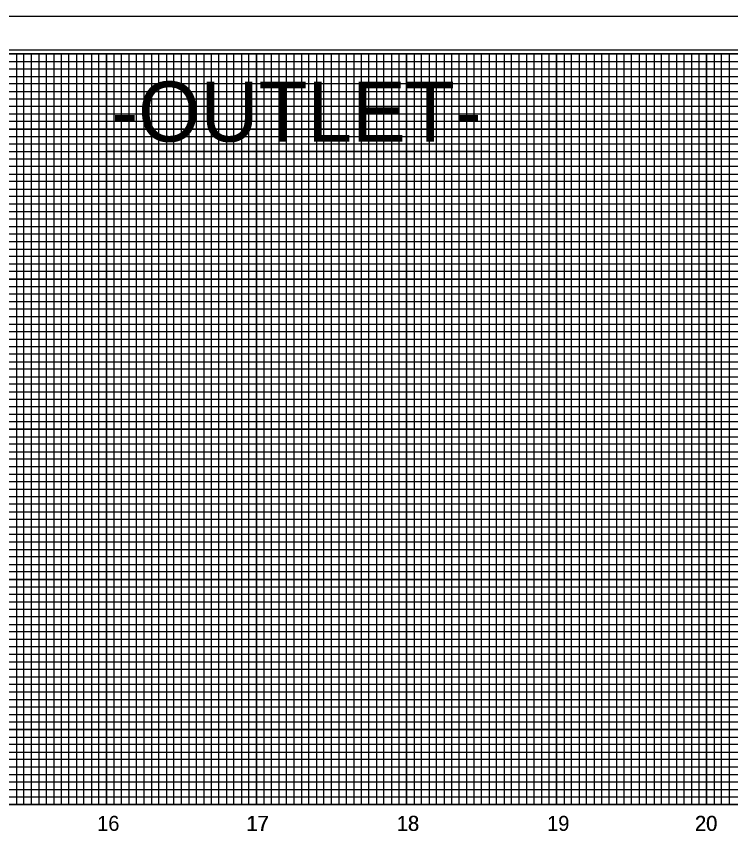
# Model space of a CAD drawing. Extents: x 1779926 to 1781610, y 602514 to 621564.
# Drawn here: x 1780683 to 1781159, y 603068 to 603614 of the extents above; entities that cross this region are included whole.
import ezdxf

# ---------------------------------------------------------------- set-up
doc = ezdxf.new("R2010")
doc.units = 0
for name, color, linetype in [('Exist Vertical Profile Horizontal Axis Label Major', 7, 'Continuous'), ('Exist Vertical Profile Vertical Axis Label', 7, 'Continuous'), ('Prop Grid Mask', 7, 'Continuous'), ('Scratch_Level_0', 7, 'Continuous'), ('Sheet DOT Grid CELL', 7, 'Continuous'), ('Sheet Layout Profile Border Port 1', 7, 'Continuous'), ('Sheet Plot Border Inside CELL', 7, 'Continuous'), ('Sheet Plot Border Outside CELL', 7, 'Continuous'), ('Sheet Profile CELL', 7, 'Continuous'), ('Sheet Profile Grid Major CELL', 7, 'Continuous'), ('Sheet Profile Grid Middle CELL', 7, 'Continuous'), ('Sheet Profile Grid Minor CELL', 7, 'Continuous')]:
    doc.layers.add(name, color=color, linetype=linetype)

msp = doc.modelspace()

# ---------------------------------------------------------------- linework, layer by layer
at = {"layer": 'Prop Grid Mask'}
msp.add_lwpolyline([(1780742.96, 603574.45), (1780997.96, 603574.45), (1780997.96, 603524.45), (1780742.96, 603524.45)], close=True, dxfattribs=at)
at = {"layer": 'Scratch_Level_0'}
msp.add_lwpolyline([(1780142.96, 603089.44), (1780142.96, 603589.44), (1781392.96, 603589.44), (1781392.96, 603364.44), (1781542.96, 603364.44), (1781542.96, 603089.44)], close=True, dxfattribs=at)
at = {"layer": 'Sheet DOT Grid CELL'}
for p, q in [((1780692.96, 603089.45), (1780692.96, 603589.45)), ((1780742.96, 603089.45), (1780742.96, 603589.45)), ((1780792.96, 603089.45), (1780792.96, 603589.45)), ((1780842.96, 603089.45), (1780842.96, 603589.45)), ((1780892.96, 603089.45), (1780892.96, 603589.45)), ((1780942.96, 603089.45), (1780942.96, 603589.45)), ((1780992.96, 603089.45), (1780992.96, 603589.45)), ((1781042.96, 603089.45), (1781042.96, 603589.45)), ((1781092.96, 603089.45), (1781092.96, 603589.45)), ((1781142.96, 603089.45), (1781142.96, 603589.45)), ((1781392.91, 603539.45), (1780092.96, 603539.45)), ((1781392.91, 603489.45), (1780092.96, 603489.45)), ((1781392.96, 603439.45), (1780092.96, 603439.45)), ((1781392.91, 603389.45), (1780092.96, 603389.45)), ((1781592.96, 603339.45), (1780092.96, 603339.45)), ((1781592.96, 603289.45), (1780092.96, 603289.45)), ((1781592.96, 603239.45), (1780092.96, 603239.45)), ((1781592.96, 603189.45), (1780092.96, 603189.45)), ((1781592.96, 603139.45), (1780092.96, 603139.45))]:
    msp.add_line(p, q, dxfattribs=at)
at = {"layer": 'Sheet Layout Profile Border Port 1'}
msp.add_lwpolyline([(1780142.96, 603589.44), (1781392.91, 603589.45), (1781392.9, 603364.45), (1781542.96, 603364.44), (1781542.96, 603089.45), (1780142.96, 603089.44)], close=True, dxfattribs=at)
msp.add_lwpolyline([(1780142.96, 603428.4), (1780142.96, 603089.45), (1781542.96, 603089.45), (1781542.96, 603364.45)], dxfattribs=at)
at = {"layer": 'Sheet Plot Border Inside CELL'}
msp.add_lwpolyline([(1779938.96, 602536.9), (1781605.46, 602536.9), (1781605.46, 603592), (1779938.96, 603592)], close=True, dxfattribs=at)
at = {"layer": 'Sheet Plot Border Outside CELL'}
msp.add_lwpolyline([(1779925.96, 602514.45), (1781609.96, 602514.45), (1781609.96, 603614.45), (1779925.96, 603614.45)], close=True, dxfattribs=at)
at = {"layer": 'Sheet Profile CELL'}
msp.add_line((1780092.96, 603089.45), (1781592.96, 603089.45), dxfattribs=at)
msp.add_lwpolyline([(1781592.96, 603589.45), (1780092.96, 603589.45), (1780092.96, 602539.45), (1781592.96, 602539.45)], close=True, dxfattribs=at)
at = {"layer": 'Sheet Profile Grid Major CELL'}
for points in [[(1780642.96, 603089.45), (1780692.96, 603089.45), (1780692.96, 603589.45), (1780742.96, 603589.45), (1780742.96, 603089.45), (1780792.96, 603089.45), (1780792.96, 603589.45), (1780842.96, 603589.45), (1780842.96, 603089.45), (1780892.96, 603089.45), (1780892.96, 603589.45), (1780942.96, 603589.45), (1780942.96, 603089.45), (1780992.96, 603089.45), (1780992.96, 603589.45), (1781042.96, 603589.45), (1781042.96, 603089.45), (1781092.96, 603089.45), (1781092.96, 603589.45), (1781142.96, 603589.45), (1781142.96, 603089.45), (1781192.96, 603089.45)], [(1780092.96, 603539.45), (1781392.96, 603539.45)], [(1781392.96, 603489.45), (1780092.96, 603489.45), (1780092.96, 603439.45), (1781392.96, 603439.45)], [(1781392.91, 603389.45), (1780092.96, 603389.45), (1780092.96, 603339.45), (1781592.96, 603339.45)], [(1781592.96, 603289.45), (1780092.96, 603289.45), (1780092.96, 603239.45), (1781592.96, 603239.45)], [(1781592.96, 603189.45), (1780092.96, 603189.45), (1780092.96, 603189.45), (1780092.96, 603139.45), (1781592.96, 603139.45)]]:
    msp.add_lwpolyline(points, dxfattribs=at)
at = {"layer": 'Sheet Profile Grid Middle CELL'}
msp.add_line((1780092.96, 603564.45), (1781392.91, 603564.45), dxfattribs=at)
for points in [[(1780667.96, 603089.45), (1780717.96, 603089.45), (1780717.96, 603089.45), (1780717.96, 603589.45), (1780767.96, 603589.45), (1780767.96, 603089.45), (1780817.96, 603089.45), (1780817.96, 603589.45), (1780867.96, 603589.45), (1780867.96, 603089.45), (1780917.96, 603089.45), (1780917.96, 603589.45), (1780967.96, 603589.45), (1780967.96, 603089.45), (1781017.96, 603089.45), (1781017.96, 603589.45), (1781067.96, 603589.45), (1781067.96, 603089.45), (1781117.96, 603089.45), (1781117.96, 603589.45), (1781167.96, 603589.45)], [(1781392.96, 603514.45), (1780092.96, 603514.45), (1780092.96, 603464.45), (1781392.96, 603464.45)], [(1781392.91, 603414.45), (1780092.96, 603414.45), (1780092.96, 603364.45), (1781417.96, 603364.45)], [(1781592.96, 603314.45), (1780092.96, 603314.45), (1780092.96, 603264.45), (1781592.96, 603264.45)], [(1781592.96, 603214.45), (1780092.96, 603214.45), (1780092.96, 603164.45), (1781592.96, 603164.45)], [(1781592.96, 603114.45), (1780092.96, 603114.45)]]:
    msp.add_lwpolyline(points, dxfattribs=at)
at = {"layer": 'Sheet Profile Grid Minor CELL'}
for p, q in [((1780142.96, 603584.45), (1781392.96, 603584.45)), ((1781392.96, 603579.45), (1780142.96, 603579.1)), ((1780142.96, 603574.45), (1781392.96, 603574.45)), ((1781392.91, 603454.45), (1780142.96, 603454.45)), ((1781392.96, 603449.45), (1780142.96, 603449.45)), ((1781392.96, 603444.45), (1780142.96, 603444.45)), ((1780142.96, 603434.45), (1781392.96, 603434.45)), ((1781392.96, 603429.45), (1780142.96, 603429.45)), ((1780142.96, 603424.45), (1781392.96, 603424.45)), ((1781392.96, 603404.45), (1780142.96, 603404.45)), ((1780142.96, 603399.45), (1781392.96, 603399.45)), ((1781392.91, 603379.45), (1780142.96, 603379.45)), ((1780142.96, 603374.45), (1781392.91, 603374.45)), ((1781542.96, 603354.45), (1780142.96, 603354.45)), ((1780142.96, 603349.45), (1781542.96, 603349.45)), ((1781542.96, 603344.45), (1780142.96, 603344.45)), ((1780142.96, 603334.45), (1781542.96, 603334.45)), ((1781542.96, 603329.45), (1780142.96, 603329.45)), ((1780142.96, 603324.45), (1781542.96, 603324.45)), ((1781542.96, 603319.45), (1780142.96, 603319.45)), ((1780142.96, 603309.45), (1781542.96, 603309.45)), ((1781542.96, 603304.45), (1780142.96, 603304.45)), ((1780142.96, 603299.45), (1781542.96, 603299.45)), ((1781542.96, 603294.45), (1780142.96, 603294.45)), ((1780142.96, 603284.45), (1781542.96, 603284.45)), ((1781542.96, 603279.45), (1780142.96, 603279.45)), ((1780142.96, 603274.45), (1781542.96, 603274.45)), ((1781542.96, 603269.45), (1780142.96, 603269.45)), ((1780142.96, 603259.45), (1781542.96, 603259.45)), ((1781542.96, 603254.45), (1780142.96, 603254.45)), ((1780142.96, 603249.45), (1781542.96, 603249.45)), ((1781542.96, 603244.45), (1780142.96, 603244.45)), ((1780142.96, 603234.45), (1781542.96, 603234.45)), ((1781542.96, 603229.45), (1780142.96, 603229.45)), ((1780142.96, 603224.45), (1781542.96, 603224.45)), ((1781542.96, 603219.45), (1780142.96, 603219.45)), ((1780142.96, 603209.45), (1781542.96, 603209.45)), ((1781542.96, 603204.45), (1780142.96, 603204.45)), ((1781542.96, 603199.45), (1780142.96, 603199.45)), ((1781542.96, 603194.45), (1780142.96, 603194.45)), ((1780142.96, 603184.45), (1781542.96, 603184.45)), ((1781542.96, 603179.45), (1780142.96, 603179.45)), ((1780142.96, 603174.45), (1781542.96, 603174.45)), ((1781542.96, 603169.45), (1780142.96, 603169.45)), ((1780142.96, 603159.45), (1781542.96, 603159.45)), ((1781542.96, 603154.45), (1780142.96, 603154.45)), ((1780142.96, 603149.45), (1781542.96, 603149.45)), ((1781542.96, 603144.45), (1780142.96, 603144.45)), ((1780142.96, 603134.45), (1781542.96, 603134.45)), ((1781542.96, 603129.45), (1780142.96, 603129.45)), ((1780142.96, 603124.45), (1781542.96, 603124.45)), ((1781542.96, 603119.45), (1780142.96, 603119.45)), ((1780142.96, 603109.45), (1781542.96, 603109.45)), ((1781542.96, 603104.45), (1780142.96, 603104.45)), ((1780142.96, 603099.45), (1781542.96, 603099.45))]:
    msp.add_line(p, q, dxfattribs=at)
for points in [[(1780677.96, 603589.45), (1780682.96, 603589.45), (1780682.96, 603089.45), (1780687.96, 603089.45), (1780687.96, 603589.45), (1780697.96, 603589.45), (1780697.96, 603089.45), (1780702.96, 603089.45), (1780702.96, 603589.45), (1780707.96, 603589.45), (1780707.96, 603089.45), (1780712.96, 603089.45), (1780712.96, 603589.45), (1780722.96, 603589.45), (1780722.96, 603089.45), (1780727.96, 603089.45), (1780727.96, 603589.45), (1780732.96, 603589.45), (1780732.96, 603089.45), (1780737.96, 603089.45), (1780737.96, 603589.45), (1780747.96, 603589.45), (1780747.96, 603089.45), (1780752.96, 603089.45), (1780752.96, 603589.45), (1780757.96, 603589.45), (1780757.96, 603089.45), (1780762.96, 603089.45), (1780762.96, 603589.45), (1780772.96, 603589.45), (1780772.96, 603089.45), (1780777.96, 603089.45), (1780777.96, 603589.45), (1780782.96, 603589.45), (1780782.96, 603089.45), (1780787.96, 603089.45), (1780787.96, 603589.45), (1780797.96, 603589.45), (1780797.96, 603089.45), (1780797.96, 603089.45), (1780802.96, 603089.45), (1780802.96, 603589.45), (1780807.96, 603589.45), (1780807.96, 603089.45), (1780812.96, 603089.45), (1780812.96, 603589.45), (1780822.96, 603589.45), (1780822.96, 603089.45), (1780827.96, 603089.45), (1780827.96, 603589.45), (1780832.96, 603589.45), (1780832.96, 603089.45), (1780837.96, 603089.45), (1780837.96, 603589.45), (1780847.96, 603589.45), (1780847.96, 603089.45), (1780852.96, 603089.45), (1780852.96, 603589.45), (1780857.96, 603589.45), (1780857.96, 603089.45), (1780862.96, 603089.45), (1780862.96, 603589.45), (1780872.96, 603589.45), (1780872.96, 603089.45), (1780877.96, 603089.45), (1780877.96, 603589.45), (1780882.96, 603589.45), (1780882.96, 603089.45), (1780887.96, 603089.45), (1780887.96, 603589.45), (1780897.96, 603589.45), (1780897.96, 603089.45), (1780902.96, 603089.45), (1780902.96, 603589.45), (1780907.96, 603589.45), (1780907.96, 603089.45), (1780912.96, 603089.45), (1780912.96, 603589.45), (1780922.96, 603589.45), (1780922.96, 603089.45), (1780927.96, 603089.45), (1780927.96, 603589.45), (1780932.96, 603589.45), (1780932.96, 603089.45), (1780937.96, 603089.45), (1780937.96, 603589.45), (1780947.96, 603589.45), (1780947.96, 603089.45), (1780952.66, 603090), (1780952.96, 603089.45), (1780952.96, 603589.45), (1780957.96, 603589.45), (1780957.96, 603089.45), (1780962.96, 603089.45), (1780962.96, 603589.45), (1780972.96, 603589.45), (1780972.96, 603089.45), (1780977.96, 603089.45)], [(1780977.96, 603089.45), (1780977.96, 603589.45), (1780982.96, 603589.45), (1780982.96, 603089.45), (1780987.96, 603089.45), (1780987.96, 603589.45), (1780997.96, 603589.45), (1780997.96, 603089.45), (1781002.96, 603089.45), (1781002.96, 603589.45), (1781007.96, 603589.45), (1781007.96, 603089.45), (1781012.96, 603089.45), (1781012.96, 603589.45), (1781022.96, 603589.45), (1781022.96, 603089.45), (1781027.96, 603089.45), (1781027.96, 603589.45), (1781032.96, 603589.45), (1781032.96, 603089.45), (1781037.96, 603089.45), (1781037.96, 603589.45), (1781047.96, 603589.45), (1781047.96, 603089.45), (1781052.96, 603089.45), (1781052.96, 603589.45), (1781057.96, 603589.45), (1781057.96, 603089.45), (1781062.96, 603089.45), (1781062.96, 603589.45), (1781072.96, 603589.45), (1781072.96, 603089.45), (1781077.96, 603089.45), (1781077.96, 603589.45), (1781082.96, 603589.45), (1781082.96, 603089.45), (1781087.96, 603089.45), (1781087.96, 603589.45), (1781097.96, 603589.45), (1781097.96, 603089.45), (1781102.96, 603089.45), (1781102.96, 603589.45), (1781107.96, 603589.45), (1781107.96, 603089.45), (1781112.96, 603089.45), (1781112.96, 603589.45), (1781122.96, 603589.45), (1781122.96, 603089.45), (1781127.96, 603089.45), (1781127.96, 603589.45), (1781132.96, 603589.45), (1781132.96, 603089.45), (1781137.96, 603089.45), (1781137.96, 603589.45), (1781147.96, 603589.45), (1781147.96, 603089.45), (1781152.96, 603089.45), (1781152.96, 603589.45), (1781157.96, 603589.45), (1781157.96, 603089.45), (1781162.96, 603089.45)], [(1781392.96, 603569.45), (1780142.96, 603569.45), (1780142.96, 603559.45), (1781392.96, 603559.45)], [(1781392.91, 603554.45), (1780142.96, 603554.45), (1780142.96, 603549.45), (1781392.96, 603549.45)], [(1781392.96, 603544.45), (1780142.96, 603544.45), (1780142.96, 603534.45), (1781392.96, 603534.45)], [(1781392.96, 603529.45), (1780142.96, 603529.45), (1780142.96, 603524.45), (1781392.96, 603524.45)], [(1781392.96, 603519.45), (1780142.96, 603519.45), (1780142.96, 603509.45), (1781392.96, 603509.45)], [(1781392.96, 603504.45), (1780142.96, 603504.45), (1780142.96, 603499.45), (1781392.96, 603499.45)], [(1781392.96, 603494.45), (1780142.96, 603494.45), (1780142.96, 603484.45), (1781392.96, 603484.45)], [(1781392.96, 603479.35), (1780143.06, 603479.35), (1780143.06, 603474.45), (1781392.96, 603474.45)], [(1781392.96, 603469.45), (1780142.96, 603469.45), (1780142.96, 603459.45), (1781392.96, 603459.45)], [(1781392.91, 603419.45), (1780142.96, 603419.45), (1780142.96, 603409.45), (1781392.91, 603409.45)], [(1781392.91, 603394.45), (1780142.96, 603394.45), (1780142.96, 603384.45), (1781392.91, 603384.45)], [(1781392.91, 603369.45), (1780142.96, 603369.45), (1780142.96, 603359.45), (1781542.96, 603359.45)], [(1781542.96, 603094.45), (1780142.96, 603094.45)]]:
    msp.add_lwpolyline(points, dxfattribs=at)

# ---------------------------------------------------------------- texts
at = {"layer": 'Exist Vertical Profile Horizontal Axis Label Major'}
for s, p in [('16', (1780736.76, 603071.95)), ('17', (1780836.18, 603071.95)), ('17', (1780836.18, 603071.95)), ('17', (1780836.5, 603071.95)), ('18', (1780936.4, 603071.95)), ('18', (1780936.4, 603071.95)), ('18', (1780936.63, 603071.95)), ('19', (1781036.63, 603071.95)), ('19', (1781036.63, 603071.95)), ('19', (1781036.67, 603071.95)), ('20', (1781135.13, 603071.95)), ('20', (1781135.13, 603071.95)), ('20', (1781135.35, 603071.95))]:
    msp.add_text(s, height=10, dxfattribs=at).set_placement(p)
at = {"layer": 'Exist Vertical Profile Vertical Axis Label'}
msp.add_text('-OUTLET-', height=40, dxfattribs=at).set_placement((1780746.27, 603531.04))

doc.saveas('drawing.dxf')
